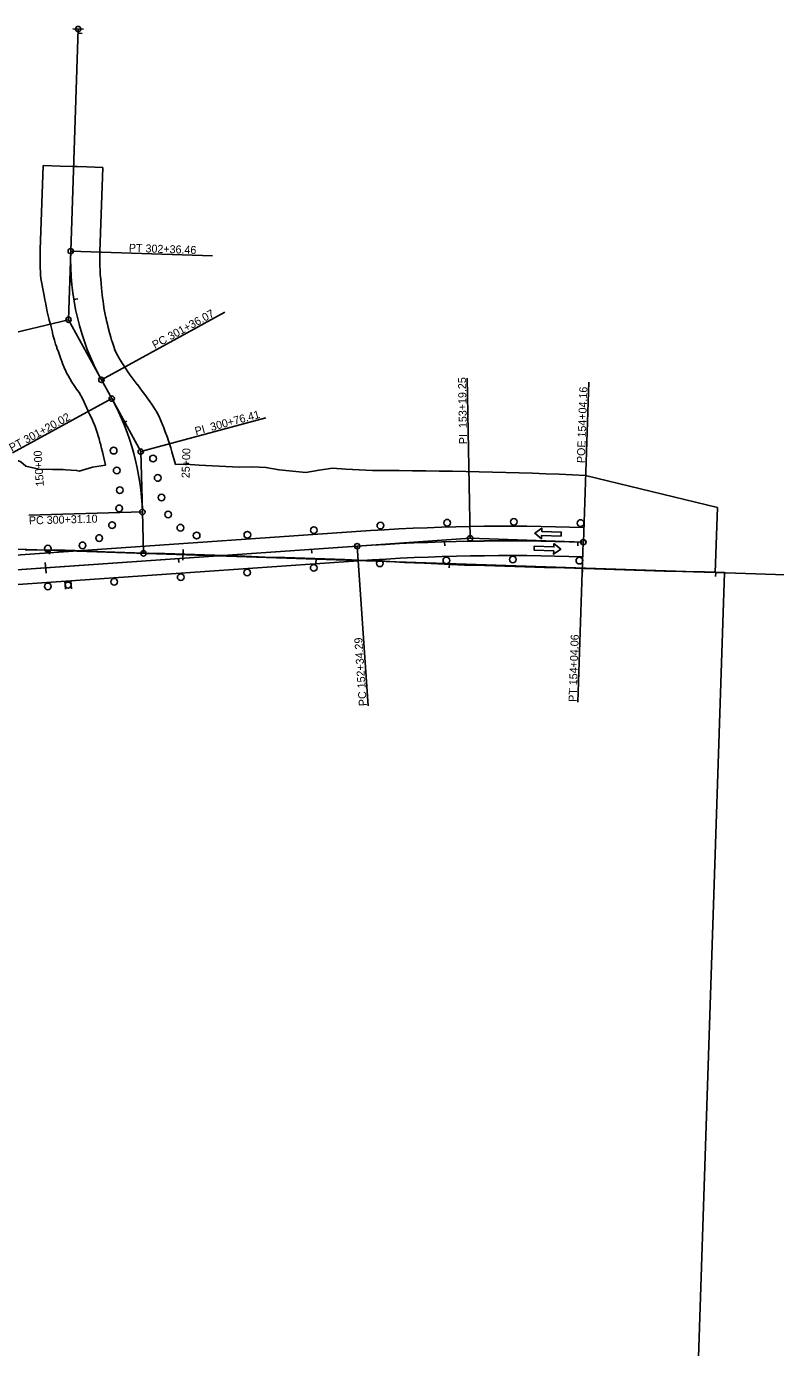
# Model space of a CAD drawing. Extents: x 976638 to 988477, y 1524676 to 1528093.
# Drawn here: x 978331 to 978893, y 1525867 to 1526858 of the extents above; entities that cross this region are included whole.
import ezdxf

# ---------------------------------------------------------------- set-up
doc = ezdxf.new("R2010")
doc.units = 0
for name, color, linetype in [('R_Draft', 7, 'Continuous'), ('R_Horz Alg', 7, 'Continuous'), ('R_Horz Alg Annot', 7, 'Continuous'), ('R_MOT', 7, 'Continuous'), ('R_No Plot', 7, 'Continuous'), ('R_Proposed Road_Lane', 7, 'Continuous'), ('R_Striping', 7, 'Continuous')]:
    doc.layers.add(name, color=color, linetype=linetype)

msp = doc.modelspace()

# ---------------------------------------------------------------- linework, layer by layer
at = {"layer": 'R_Draft'}
for p, q in [((978341.68, 1526690.49), (978343.79, 1526753.82)), ((978343.79, 1526753.82), (978356.7, 1526753.39)), ((978356.7, 1526753.39), (978376.69, 1526752.72)), ((978376.69, 1526752.72), (978388.56, 1526752.33)), ((978388.56, 1526752.33), (978386.44, 1526689)), ((978750.88, 1526521.42), (978849.74, 1526497.2)), ((978849.74, 1526497.2), (978848.11, 1526448.56))]:
    msp.add_line(p, q, dxfattribs=at)
for points in [[(978373.73, 1526578.55), (978370.86, 1526583.67), (978368.91, 1526586.12), (978368.07, 1526587.35), (978367.16, 1526588.7), (978365.46, 1526591.32), (978363.83, 1526593.98), (978362.29, 1526596.69), (978362.21, 1526596.82), (978360.83, 1526599.45), (978359.66, 1526602.33), (978358.48, 1526605.21), (978357.76, 1526607.01), (978357.35, 1526608.11), (978356.28, 1526611.03), (978355.25, 1526613.97), (978354.24, 1526616.92), (978354.04, 1526617.49), (978353.24, 1526619.86), (978352.29, 1526622.83), (978351.48, 1526625.83), (978350.94, 1526628.16), (978350.78, 1526628.87), (978350.11, 1526631.91), (978349.34, 1526634.92), (978348.49, 1526637.91), (978348.22, 1526638.93), (978347.7, 1526640.93), (978346.97, 1526643.96), (978346.44, 1526647.03), (978345.95, 1526649.82), (978345.88, 1526650.09), (978345.18, 1526653.14), (978344.53, 1526656.2), (978342.05, 1526669.07)], [(978387.75, 1526661.84), (978387.95, 1526659.37), (978388.2, 1526656.9), (978388.22, 1526656.68), (978388.47, 1526654.43), (978388.79, 1526651.97), (978389.13, 1526649.5), (978389.37, 1526647.87), (978389.5, 1526647.04), (978389.91, 1526644.58), (978390.36, 1526642.13), (978390.91, 1526639.69), (978391.04, 1526639.13), (978391.48, 1526637.26), (978392.06, 1526634.84), (978392.63, 1526632.4), (978393.12, 1526630.44), (978393.24, 1526629.96), (978393.87, 1526627.54), (978394.54, 1526625.11), (978395.24, 1526622.7), (978395.51, 1526621.78), (978396.02, 1526620.3), (978396.87, 1526617.94), (978397.75, 1526615.58), (978398.66, 1526613.37)], [(978398.66, 1526613.37), (978398.72, 1526613.26), (978399.92, 1526611.04), (978401.16, 1526608.85), (978402.45, 1526606.68), (978403.13, 1526605.56), (978403.76, 1526604.54), (978405.12, 1526602.43), (978408.29, 1526597.48), (978414.39, 1526589.63), (978414.52, 1526589.46), (978416.3, 1526587.12), (978418.2, 1526584.59), (978420.1, 1526582.03), (978421.33, 1526580.35), (978421.97, 1526579.45), (978423.81, 1526576.83), (978425.62, 1526574.18), (978427.37, 1526571.49), (978427.78, 1526570.84), (978429.13, 1526568.78), (978430.66, 1526565.96), (978431.94, 1526563.04), (978432.96, 1526560.62), (978433.18, 1526560.1), (978434.37, 1526557.13), (978435.52, 1526554.15), (978436.61, 1526551.14), (978437.04, 1526549.91), (978437.66, 1526548.12), (978438.65, 1526545.07), (978439.6, 1526542.01), (978440.49, 1526538.95), (978440.49, 1526538.93), (978443.07, 1526529.48)], [(978390.58, 1526529.01), (978388.32, 1526539.1), (978387.74, 1526541.5), (978387.14, 1526543.9), (978387.03, 1526544.32), (978386.5, 1526546.29), (978385.83, 1526548.68), (978385.11, 1526551.06), (978384.55, 1526552.87), (978384.37, 1526553.43), (978383.58, 1526555.8), (978382.77, 1526558.15), (978381.81, 1526560.45), (978381.47, 1526561.25), (978380.82, 1526562.74), (978379.79, 1526565.01), (978378.73, 1526567.26), (978377.71, 1526569.35), (978377.64, 1526569.5), (978373.73, 1526578.55)], [(978321.06, 1526534.08), (978327.13, 1526531.64), (978330.87, 1526528.37), (978340.72, 1526526.01)], [(978443.07, 1526529.48), (978450.99, 1526529.73), (978460.97, 1526529.12), (978470.96, 1526528.56), (978480.95, 1526527.97), (978490.94, 1526527.63), (978500.95, 1526527.68), (978510.94, 1526527.38), (978520.88, 1526525.49), (978530.86, 1526524.6), (978540.83, 1526523.54), (978550.9, 1526525.31), (978560.95, 1526526.71), (978570.93, 1526526.09), (978580.92, 1526525.47), (978590.91, 1526525.12), (978600.91, 1526525.04), (978610.92, 1526524.94), (978620.92, 1526524.85), (978630.92, 1526524.77), (978640.92, 1526524.67), (978650.93, 1526524.54), (978660.92, 1526524.3), (978670.92, 1526524.05), (978680.92, 1526523.81), (978690.92, 1526523.56), (978700.91, 1526523.32), (978710.91, 1526522.96), (978720.9, 1526522.61), (978730.89, 1526522.18), (978740.89, 1526521.84), (978750.88, 1526521.42)], [(978340.72, 1526526.01), (978350.8, 1526525.91), (978358.95, 1526525.77), (978360.8, 1526525.65), (978368.94, 1526525.11), (978370.83, 1526524.65)], [(978370.83, 1526524.65), (978380.88, 1526527.62), (978390.58, 1526529.01)], [(978848.11, 1526448.56), (978750.1, 1526451.55), (978735.1, 1526452.02), (978720.11, 1526452.42), (978705.12, 1526452.89), (978690.12, 1526453.22), (978675.03, 1526453.72), (978660.04, 1526454.15), (978645.05, 1526454.87), (978630.07, 1526455.58), (978615.08, 1526455.98), (978600.1, 1526457.01), (978585.12, 1526457.67), (978570.18, 1526458.21), (978555.19, 1526458.77), (978540.2, 1526459.34), (978525.21, 1526459.79), (978510.21, 1526460.05), (978495.22, 1526460.73), (978480.23, 1526461.31), (978465.24, 1526461.76), (978450.25, 1526462.28), (978435.26, 1526462.73), (978420.26, 1526463.09), (978405.24, 1526463.63), (978390.24, 1526464.15), (978375.26, 1526464.78), (978360.38, 1526465.18), (978345.38, 1526465.29), (978330.39, 1526465.66)]]:
    msp.add_lwpolyline(points, dxfattribs=at)
for radius, end in [(211.48, 183.89411), (166.69, 187.4415)]:
    msp.add_arc((978553.04, 1526683.43), radius, 178.08523, end, dxfattribs=at)
at = {"layer": 'R_Horz Alg'}
for p, q in [((978364.57, 1526689.54), (978370.14, 1526856.1)), ((978395.26, 1526578.96), (978387.56, 1526593.03)), ((976649.72, 1526521.99), (979428.17, 1526429.1)), ((978419.14, 1526462.84), (978418.28, 1526493.93)), ((978749.11, 1526471.32), (978749.2, 1526471.32)), ((978320.48, 1526450.29), (978579.44, 1526468.32))]:
    msp.add_line(p, q, dxfattribs=at)
for centre, radius, start, end in [((978552.32, 1526683.26), 187.85, 178.08523, 208.70575), ((978230.49, 1526488.73), 187.86, 1.58523, 28.70575), ((978693.16, 1524835.26), 1637.02, 88.04134, 93.98333)]:
    msp.add_arc(centre, radius, start, end, dxfattribs=at)
at = {"layer": 'R_Horz Alg Annot'}
for p, q in [((978362.86, 1526638.14), (978364.57, 1526689.54)), ((978387.56, 1526593.03), (978362.86, 1526638.14)), ((978417.02, 1526539.22), (978395.26, 1526578.96)), ((978418.28, 1526493.93), (978417.02, 1526539.22)), ((978579.44, 1526468.32), (978664.19, 1526474.23)), ((978664.19, 1526474.23), (978749.11, 1526471.32))]:
    msp.add_line(p, q, dxfattribs=at)
for points in [[(978366.15, 1526856.24), (978374.14, 1526855.97)], [(978373.04, 1526852.88), (978370.04, 1526852.98)], [(978369.7, 1526752.94), (978366.7, 1526753.04)], [(978364.57, 1526689.54), (978471, 1526685.98)], [(978369.85, 1526653.69), (978366.89, 1526653.21)], [(978387.56, 1526593.03), (978480.21, 1526643.77)], [(978362.86, 1526638.14), (978271.55, 1526616.39)], [(978664.19, 1526474.23), (978662.07, 1526594.21)], [(978749.2, 1526471.32), (978753.3, 1526591.25)], [(978395.26, 1526578.96), (978320.82, 1526538.2)], [(978406.7, 1526562.07), (978403.93, 1526560.92)], [(978417.02, 1526539.22), (978510.87, 1526564.62)], [(978418.28, 1526493.93), (978333.06, 1526491.57)], [(978645.15, 1526468.57), (978645.06, 1526471.57)], [(978744.95, 1526468.46), (978745.05, 1526471.46)], [(978749.11, 1526471.32), (978745, 1526351.39)], [(978348.67, 1526462.19), (978348.77, 1526465.19)], [(978415.14, 1526462.73), (978423.14, 1526462.95)], [(978448.85, 1526465.85), (978448.58, 1526457.85)], [(978545.44, 1526462.95), (978545.23, 1526465.94)], [(978579.44, 1526468.32), (978587.77, 1526348.61)], [(978345.44, 1526456.04), (978345.99, 1526448.06)], [(978445.68, 1526456), (978445.47, 1526459)], [(978548.56, 1526455.51), (978548.66, 1526458.51)], [(978648.51, 1526452.17), (978648.61, 1526455.16)], [(978748.45, 1526448.83), (978748.55, 1526451.82)], [(978848.39, 1526445.48), (978848.49, 1526448.48)]]:
    msp.add_lwpolyline(points, dxfattribs=at)
for centre in [(978370.14, 1526856.1), (978364.57, 1526689.54), (978362.86, 1526638.14), (978387.56, 1526593.03), (978395.26, 1526578.96), (978417.02, 1526539.22), (978418.28, 1526493.93), (978579.44, 1526468.32), (978664.19, 1526474.23), (978749.11, 1526471.32), (978749.2, 1526471.32), (978419.14, 1526462.84)]:
    msp.add_circle(centre, 2, dxfattribs=at)
at = {"layer": 'R_MOT'}
for p, q in [((978360.53, 1526435.99), (978360.13, 1526441.97)), ((978364.62, 1526442.27), (978365.02, 1526436.28))]:
    msp.add_line(p, q, dxfattribs=at)
for centre, radius in [((978396.75, 1526539.94), 2.5), ((978426.28, 1526534.04), 2.5), ((978399.04, 1526525.11), 2.5), ((978429.79, 1526519.46), 2.5), ((978401.33, 1526510.29), 2.5), ((978432.69, 1526504.74), 2.5), ((978400.91, 1526496.65), 2.5), ((978437.61, 1526492.1), 2.5), ((978395.53, 1526484.1), 2.5), ((978446.81, 1526482.14), 2.5), ((978546.93, 1526480.33), 2.5), ((978596.86, 1526483.7), 2.5), ((978646.91, 1526485.87), 2.5), ((978697, 1526486.51), 2.5), ((978747.09, 1526485.63), 2.5), ((978373.44, 1526468.9), 2.5), ((978385.92, 1526474.4), 2.5), ((978459.02, 1526476.25), 2.5), ((978497.05, 1526476.85), 2.5), ((978347.42, 1526466.43), 2.5), ((978646.35, 1526457.64), 2.5), ((978696.25, 1526458.31), 2.5), ((978496.95, 1526448.58), 2.5), ((978546.83, 1526452.06), 2.5), ((978596.49, 1526455.44), 2.5), ((978746.15, 1526457.44), 2.5), ((978347.31, 1526438.16), 2.5), ((978362.57, 1526439.13), 2.25), ((978362.57, 1526439.13), 2.25), ((978397.19, 1526441.64), 2.5), ((978447.07, 1526445.11), 2.5)]:
    msp.add_circle(centre, radius, dxfattribs=at)
at = {"layer": 'R_No Plot'}
msp.add_line((978827.55, 1525623.52), (978855.06, 1526448.49), dxfattribs=at)
msp.add_line((978827.55, 1525623.52), (978855.06, 1526448.49), dxfattribs=at)
msp.add_lwpolyline([(978855.06, 1526448.49), (978840.07, 1526449), (978825.08, 1526449.38), (978810.08, 1526449.61), (978795.08, 1526450.08), (978780.09, 1526450.53), (978765.09, 1526451.09), (978750.1, 1526451.55), (978735.1, 1526452.02), (978720.11, 1526452.42), (978705.12, 1526452.89), (978690.12, 1526453.22), (978675.03, 1526453.72), (978660.04, 1526454.15), (978645.05, 1526454.87), (978630.07, 1526455.58), (978615.08, 1526455.98), (978600.1, 1526457.01), (978585.12, 1526457.67), (978570.18, 1526458.21), (978555.19, 1526458.77), (978540.2, 1526459.34), (978525.21, 1526459.79), (978510.21, 1526460.05), (978495.22, 1526460.73), (978480.23, 1526461.31), (978465.24, 1526461.76), (978450.25, 1526462.28), (978435.26, 1526462.73), (978420.26, 1526463.09), (978405.24, 1526463.63), (978390.24, 1526464.15), (978375.26, 1526464.78), (978360.38, 1526465.18), (978345.38, 1526465.29), (978330.39, 1526465.66)], dxfattribs=at)
msp.add_lwpolyline([(978855.06, 1526448.49), (978840.07, 1526449), (978825.08, 1526449.38), (978810.08, 1526449.61), (978795.08, 1526450.08), (978780.09, 1526450.53), (978765.09, 1526451.09), (978750.1, 1526451.55), (978735.1, 1526452.02), (978720.11, 1526452.42), (978705.12, 1526452.89), (978690.12, 1526453.22), (978675.03, 1526453.72), (978660.04, 1526454.15), (978645.05, 1526454.87), (978630.07, 1526455.58), (978615.08, 1526455.98), (978600.1, 1526457.01), (978585.12, 1526457.67), (978570.18, 1526458.21), (978555.19, 1526458.77), (978540.2, 1526459.34), (978525.21, 1526459.79), (978510.21, 1526460.05), (978495.22, 1526460.73), (978480.23, 1526461.31), (978465.24, 1526461.76), (978450.25, 1526462.28), (978435.26, 1526462.73), (978420.26, 1526463.09), (978405.24, 1526463.63), (978390.24, 1526464.15), (978375.26, 1526464.78), (978360.38, 1526465.18), (978345.38, 1526465.29), (978330.39, 1526465.66)], dxfattribs=at)
at = {"layer": 'R_Proposed Road_Lane'}
for p, q in [((978749.48, 1526482.32), (978749.58, 1526482.31)), ((978664.19, 1526474.23), (978579.34, 1526468.32)), ((978664.19, 1526474.23), (978749.2, 1526471.31)), ((978320.48, 1526450.29), (978579.34, 1526468.32))]:
    msp.add_line(p, q, dxfattribs=at)
msp.add_arc((978693.06, 1524835.25), 1637.02, 88.0346, 93.98333, dxfattribs=at)
at = {"layer": 'R_Striping'}
for p, q in [((978578.67, 1526479.3), (978319.72, 1526461.27)), ((978320.58, 1526450.29), (978579.53, 1526468.32)), ((978321.24, 1526439.32), (978580.2, 1526457.35))]:
    msp.add_line(p, q, dxfattribs=at)
for points in [[(978717.96, 1526481.85), (978712.64, 1526478.02), (978717.7, 1526473.85), (978717.78, 1526476.35), (978732.48, 1526475.86), (978732.58, 1526478.86), (978717.88, 1526479.35)], [(978727.1, 1526470.24), (978732.13, 1526466.04), (978726.79, 1526462.24), (978726.89, 1526464.74), (978712.19, 1526465.3), (978712.3, 1526468.3), (978727, 1526467.74)]]:
    msp.add_lwpolyline(points, close=True, dxfattribs=at)
for centre, radius, start in [((978693.16, 1524835.26), 1648.02, 88.04134), ((978693.25, 1524835.26), 1637.02, 88.04134), ((978693.06, 1524835.25), 1626.02, 88.0346)]:
    msp.add_arc(centre, radius, start, 93.98333, dxfattribs=at)

# ---------------------------------------------------------------- texts
at = {"layer": 'R_Horz Alg Annot'}
for s, rotation, p in [('PT 302+36.46', 358.08523, (978408.09, 1526689.08)), ('PC 301+36.07', 28.70575, (978427.69, 1526616.15)), ('PI  153+19.25', 91.01233, (978661.95, 1526544.87)), ('POE 154+04.16', 88.04133, (978750.23, 1526530.52)), ('PI  300+76.41', 15.14549, (978458.53, 1526551.49)), ('PT 301+20.02', 28.70575, (978320.34, 1526539.07)), ('150+00', 93.98333, (978344.46, 1526513.3)), ('25+00', 88.08523, (978453.64, 1526519.22)), ('PC 300+31.10', 1.58523, (978333.25, 1526484.57)), ('PT 154+04.06', 88.04134, (978744.01, 1526351.43)), ('PC 152+34.29', 93.98333, (978586.78, 1526348.54))]:
    msp.add_text(s, height=6, rotation=rotation, dxfattribs=at).set_placement(p)

doc.saveas('drawing.dxf')
